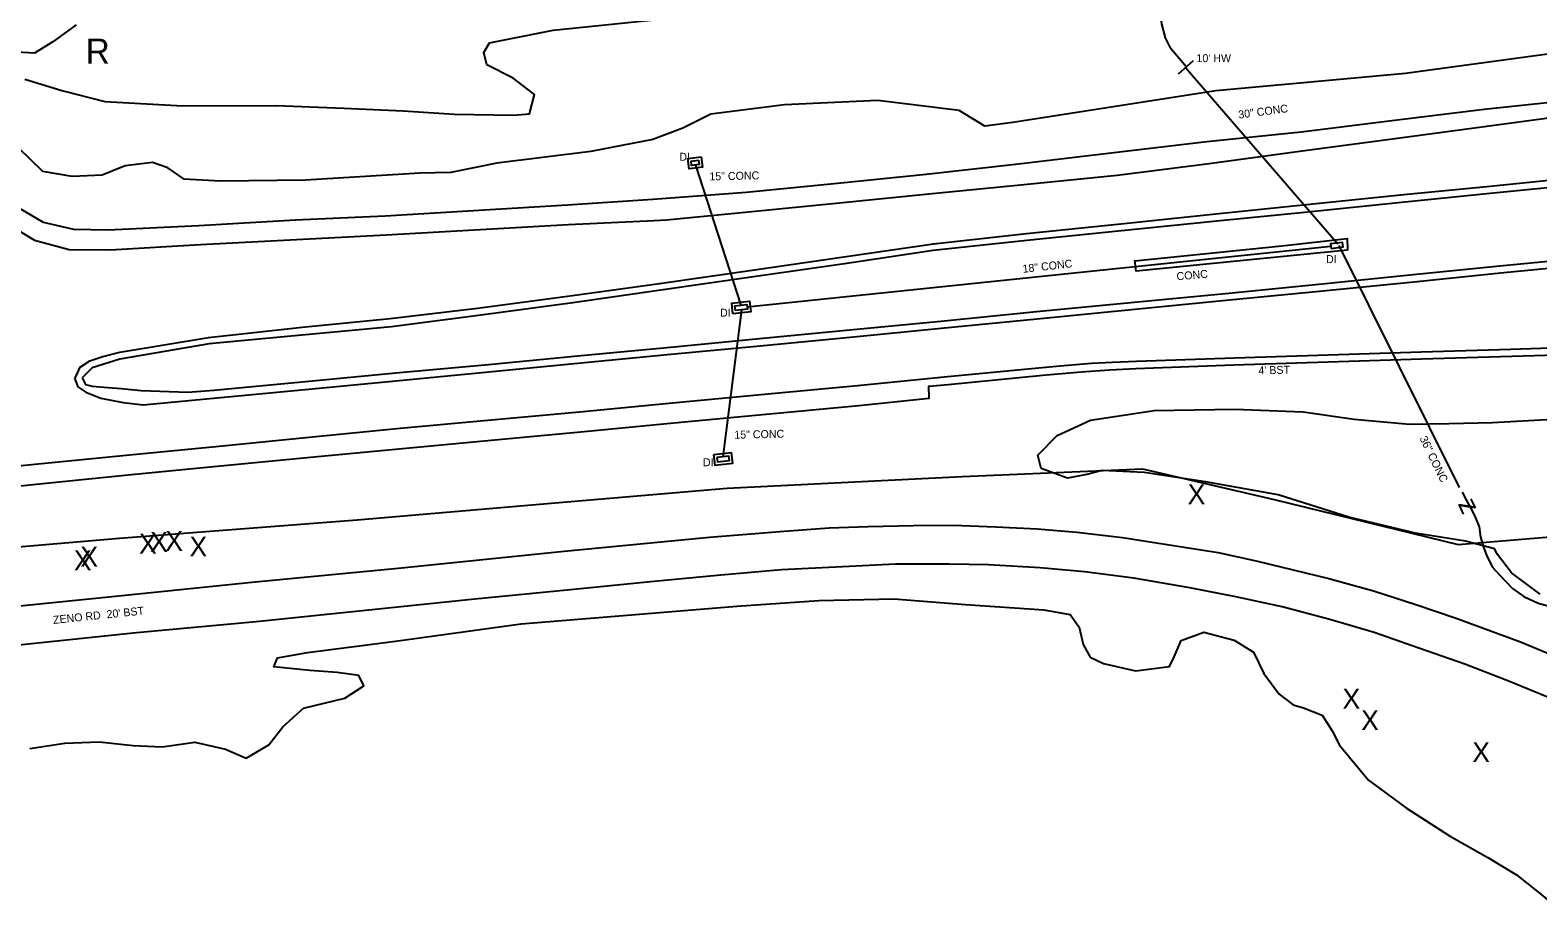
# Model space of a CAD drawing. Extents: x 2030130 to 2036320, y 723205 to 762423.
# Drawn here: x 2035001 to 2035759, y 726845 to 727287 of the extents above; entities that cross this region are included whole.
import ezdxf

# ---------------------------------------------------------------- set-up
doc = ezdxf.new("R2010")
doc.units = 0
for name, color, linetype in [('Draft_Station Labels Major', 7, 'Continuous'), ('Draft_Station Tics Major', 7, 'Continuous'), ('Draft_Station Tics Minor', 7, 'Continuous'), ('Exist Terrain Model Ground Surface', 7, 'Continuous'), ('Old_Level_23', 7, 'Continuous'), ('Old_Level_26', 7, 'Continuous'), ('Prop Alignment Horizontal', 7, 'Continuous'), ('Prop Horizontal Alignment Ramp', 7, 'Continuous')]:
    doc.layers.add(name, color=color, linetype=linetype)

msp = doc.modelspace()

# ---------------------------------------------------------------- linework, layer by layer
at = {"layer": 'Draft_Station Labels Major'}
for points in [[(2034995.67, 727197.76), (2035007.95, 727190.6), (2035023.23, 727187.12), (2035040.54, 727186.77), (2035086.21, 727188.91), (2035134.73, 727191.73), (2035179.77, 727193.68), (2035224.16, 727196.39), (2035271.27, 727199.24), (2035314.12, 727202.1), (2035361.03, 727205.55), (2035406.96, 727210.09), (2035451.37, 727214.71), (2035497.79, 727219.82), (2035545.59, 727225.46), (2035592.34, 727230.99), (2035639.71, 727235.89), (2035686.58, 727241.72), (2035731.7, 727247.24), (2035777.53, 727252.23)], [(2034987.95, 727191.14), (2035003.56, 727181.45), (2035021.04, 727176.81), (2035041.57, 727176.7), (2035086.95, 727179.28), (2035135.13, 727181.86), (2035180.16, 727184.26), (2035224.63, 727186.74), (2035271.82, 727189.31), (2035314.77, 727191.4), (2035320.99, 727191.67), (2035362.13, 727195.75), (2035407.9, 727200.25), (2035452.82, 727204.72), (2035498.77, 727209.24), (2035547.35, 727214.24), (2035593.63, 727219.94), (2035640.31, 727226.31), (2035688.19, 727232.77), (2035733, 727238.8), (2035777.64, 727244.71)], [(2035023.82, 727111.95), (2035026.5, 727117.79), (2035031.4, 727121.01), (2035037.9, 727123.09), (2035046.5, 727125.3), (2035091, 727132.65), (2035137.96, 727137.91), (2035182.15, 727142.13), (2035226.08, 727147.42), (2035273.83, 727153.8), (2035317.56, 727159.8), (2035364.11, 727166.47), (2035411.17, 727173.29), (2035455.14, 727179.73), (2035501.75, 727184.87), (2035549.16, 727189.76), (2035596.84, 727194.69), (2035642.48, 727199.49), (2035691.26, 727204.45), (2035734.59, 727208.7), (2035782.17, 727213.41)], [(2035782.01, 727209.72), (2035734.61, 727205), (2035691.81, 727200.57), (2035643.12, 727195.66), (2035597.36, 727191.03), (2035549.5, 727186.19), (2035501.94, 727181.35), (2035455, 727176.3), (2035411.56, 727169.82), (2035364.62, 727163.13), (2035318.19, 727156.47), (2035274.04, 727150.05), (2035226.67, 727143.76), (2035182.88, 727137.95), (2035137.89, 727133.79), (2035091.4, 727129.43), (2035046.51, 727121.81), (2035032.52, 727117.35), (2035027.61, 727112.33)], [(2035027.61, 727112.33), (2035029.24, 727109.03), (2035032.51, 727108.18), (2035038.43, 727107.77), (2035047.08, 727107.02), (2035057.18, 727106.07), (2035080.54, 727105.13), (2035093.62, 727106.19), (2035139.79, 727110.55), (2035185.09, 727114.88), (2035231.65, 727119.04), (2035278.17, 727123.64), (2035323.02, 727127.87), (2035367.66, 727132.16), (2035414.75, 727136.6), (2035458.8, 727140.86), (2035506.9, 727145.71), (2035554.25, 727150.24), (2035603.45, 727154.94), (2035650.24, 727159.62), (2035696.03, 727164.21), (2035741.21, 727168.77), (2035786.41, 727173.12)], [(2035023.82, 727111.95), (2035025.39, 727107.83), (2035029.35, 727105.26), (2035036.9, 727102.26), (2035048.18, 727099.99), (2035058.18, 727098.79), (2035093.58, 727102.23), (2035139.53, 727106.62), (2035185, 727110.89), (2035231.85, 727115.39), (2035278.09, 727119.87), (2035323.23, 727124.21), (2035367.97, 727128.51), (2035414.99, 727133.03), (2035459.02, 727137.29), (2035507.2, 727142.06), (2035554.49, 727146.63), (2035603.74, 727151.53), (2035650.62, 727156.11), (2035696.41, 727160.59), (2035741.57, 727165.24), (2035786.6, 727169.71)], [(2034960.25, 727064.7), (2035005.43, 727069.15), (2035051.36, 727073.76), (2035096.33, 727078.17), (2035141.5, 727082.54), (2035187.29, 727087.06), (2035233.15, 727091.27), (2035279.08, 727095.56), (2035324, 727099.79), (2035370.27, 727104.21), (2035416.85, 727108.6), (2035462.11, 727113.1), (2035509.67, 727117.57), (2035520.57, 727118.57), (2035534.52, 727119.69), (2035544.99, 727120.25), (2035557.08, 727120.75), (2035606.35, 727122.42), (2035653.26, 727123.93), (2035699.99, 727125.39), (2035745.08, 727126.81), (2035790.2, 727128.27)], [(2034961.1, 727054.42), (2035006.09, 727059.13), (2035052.31, 727063.9), (2035097.05, 727068.15), (2035142.24, 727072.54), (2035188.35, 727076.86), (2035234.75, 727081.2), (2035279.66, 727085.39), (2035324.74, 727089.82), (2035371.11, 727094.1), (2035417.66, 727098.44), (2035452.86, 727102.11), (2035452.82, 727108.22), (2035462.52, 727108.98), (2035510.06, 727113.76), (2035529.18, 727115.44), (2035543.51, 727116.48), (2035556.77, 727117.16), (2035605.94, 727118.88), (2035653.34, 727120.46), (2035700.25, 727121.9), (2035745.52, 727123.36), (2035790.68, 727124.55)], [(2034964.59, 726994.74), (2035044.23, 727002.78), (2035112.72, 727009.77), (2035186.17, 727016.86), (2035269.65, 727025.31), (2035342.58, 727032.46), (2035377.97, 727035.21), (2035402.75, 727037.03), (2035422.25, 727037.7), (2035445.03, 727038.2), (2035464.97, 727038.41), (2035486.44, 727037.59), (2035507.23, 727036.63), (2035527.03, 727034.85), (2035550.06, 727032.25), (2035572.43, 727028.74), (2035598.13, 727024.62), (2035617.8, 727020.33), (2035653.62, 727011.71), (2035676.02, 727005.4), (2035697.39, 726998.64), (2035717.56, 726991.74), (2035749.83, 726979.87), (2035770.85, 726971.22)], [(2035766.73, 726950.75), (2035743.56, 726960.22), (2035721.92, 726968.67), (2035698.93, 726976.69), (2035676.48, 726984.47), (2035654.17, 726991.11), (2035630.24, 726997.36), (2035606.99, 727002.36), (2035583.85, 727006.92), (2035555.63, 727011.76), (2035530.99, 727014.99), (2035508.73, 727017.04), (2035482.78, 727018.52), (2035463.09, 727018.85), (2035436.05, 727018.79), (2035409.42, 727017.5), (2035378.8, 727015.92), (2035348.37, 727013.33), (2035313, 727009.95), (2035274.5, 727006.07), (2035223, 727001.03), (2035176.37, 726996.33), (2035114.89, 726989.95), (2035054.86, 726984.31), (2034992.56, 726977.82)]]:
    msp.add_lwpolyline(points, dxfattribs=at)
at = {"layer": 'Draft_Station Tics Major'}
for points in [[(2034998.7, 727262.4), (2035017.39, 727256.65), (2035038.86, 727251.12), (2035078.17, 727248.92), (2035125.22, 727249.2), (2035159, 727247.85), (2035188.84, 727246.41), (2035214.36, 727244.82), (2035244.09, 727244.25), (2035252.17, 727244.99), (2035254.69, 727254.61), (2035243.92, 727262.86), (2035230.85, 727269.48), (2035229.33, 727275.68), (2035232.18, 727280.56), (2035264.12, 727286.9), (2035324.53, 727293.15)], [(2035024.58, 727289.56), (2035012.73, 727281.15), (2035003.67, 727275.38), (2034988.97, 727276.19)], [(2035769.64, 727275.69), (2035692.2, 727265.24), (2035596.89, 727256.49), (2035494.99, 727240.56), (2035480.86, 727238.7), (2035468.03, 727246.57), (2035427.22, 727251.65), (2035380.35, 727249.47), (2035343.29, 727244.74), (2035329.16, 727237.71), (2035314.15, 727232.11), (2035282.93, 727226.11), (2035235.82, 727220.15), (2035212.72, 727215.53), (2035197.14, 727215.09), (2035139.77, 727211.62), (2035097.03, 727211.17), (2035078.78, 727212.19), (2035070.57, 727217.81), (2035062.85, 727220.44), (2035049.13, 727218.89), (2035037.6, 727214.09), (2035022.49, 727213.45), (2035007.82, 727216.05), (2034995.89, 727227.54)], [(2035759.72, 727003.84), (2035745.4, 727014.46), (2035738.28, 727023.66), (2035736.77, 727026.6), (2035722.34, 727030.38), (2035697.21, 727034.45), (2035663.76, 727042.47), (2035628.2, 727053.61), (2035591.74, 727060.18), (2035560.98, 727064.95), (2035539.82, 727065.87), (2035532.16, 727063.85), (2035522.48, 727062.09), (2035509.21, 727066.84), (2035507.42, 727073.57), (2035517.19, 727083.38), (2035533.97, 727091.18), (2035565.92, 727095.93), (2035606.46, 727096.75), (2035640.77, 727095.28), (2035666.42, 727091.59), (2035694.2, 727089.2), (2035714.14, 727089.41), (2035735.9, 727089.91), (2035769.03, 727091.8)], [(2035001.3, 726926.37), (2035018.77, 726929.02), (2035036.11, 726929.62), (2035053.12, 726927.75), (2035067.67, 726927.17), (2035084.1, 726929.5), (2035099.59, 726925.92), (2035109.84, 726921.43), (2035121.21, 726928.06), (2035128.27, 726937.09), (2035138.78, 726946.54), (2035159.54, 726951.57), (2035169.05, 726957.71), (2035166.51, 726962.89), (2035155.53, 726964.48), (2035141.95, 726965.49), (2035123.87, 726967.23), (2035125.68, 726971.73), (2035140.66, 726974.45), (2035184.86, 726980.19), (2035248.03, 726988.89), (2035307.4, 726993.75), (2035356.29, 726997.7), (2035397.46, 727000.64), (2035435.19, 727001.44), (2035471.14, 726998.57), (2035510.44, 726995.86), (2035523.74, 726993.54), (2035528.22, 726987.2), (2035530.31, 726978.46), (2035533.7, 726972.11), (2035540.53, 726968.99), (2035556.54, 726965.34), (2035573.7, 726967.45), (2035575.97, 726972.38), (2035579.42, 726980.59), (2035590.85, 726984.67), (2035606.14, 726980.67), (2035615.8, 726974.71), (2035621.07, 726964), (2035628.66, 726953.64), (2035635.7, 726948.25), (2035640.99, 726946.73), (2035650.25, 726942.96), (2035655.28, 726935.22), (2035659.04, 726927.96), (2035673.64, 726910.36), (2035692.64, 726896.36), (2035714.19, 726882.41), (2035733.52, 726871.51), (2035747.91, 726862.88), (2035758.44, 726854.54), (2035770.41, 726844.78)]]:
    msp.add_lwpolyline(points, dxfattribs=at)
at = {"layer": 'Draft_Station Tics Minor'}
for p, q in [((2035578.2, 727264.97), (2035585.63, 727271.66)), ((2035335.51, 727219.23), (2035358.41, 727148.87)), ((2035361.54, 727148), (2035654.67, 727178.53)), ((2035358.66, 727146.51), (2035349.35, 727072.71))]:
    msp.add_line(p, q, dxfattribs=at)
for points in [[(2035581.89, 727268.12), (2035658.24, 727179.69)], [(2035658.63, 727178.91), (2035719.09, 727057.27)]]:
    msp.add_lwpolyline(points, dxfattribs=at)
for points in [[(2035337.11, 727221.68), (2035337.4, 727219.48), (2035333.62, 727218.98), (2035333.33, 727221.18)], [(2035663.1, 727176.42), (2035556.83, 727165.95), (2035556.19, 727171.16), (2035630.09, 727178.75), (2035662.88, 727182.39)], [(2035654.8, 727177.39), (2035660.85, 727178.1), (2035660.59, 727180.38), (2035654.54, 727179.66)], [(2035355.65, 727146.2), (2035355.4, 727148.55), (2035361.42, 727149.18), (2035361.67, 727146.83)], [(2035346.34, 727072.37), (2035346.58, 727070.21), (2035352.61, 727070.88), (2035352.37, 727073.05)]]:
    msp.add_lwpolyline(points, close=True, dxfattribs=at)
at = {"layer": 'Exist Terrain Model Ground Surface'}
for points in [[(2035338.4, 727223.36), (2035339.09, 727218.19), (2035332.33, 727217.3), (2035331.65, 727222.47)], [(2035354.31, 727144.55), (2035353.76, 727149.89), (2035362.76, 727150.83), (2035363.31, 727145.49)], [(2035344.68, 727073.7), (2035345.25, 727068.55), (2035354.27, 727069.56), (2035353.69, 727074.71)]]:
    msp.add_lwpolyline(points, close=True, dxfattribs=at)
msp.add_lwpolyline([(2034965.98, 727025.07), (2035046.29, 727031.85), (2035165.59, 727041.12), (2035265.08, 727049.68), (2035351.44, 727057.07), (2035469.57, 727062.82), (2035560.06, 727066.76), (2035626.11, 727051.39), (2035718.65, 727028.67), (2035867.23, 727041.07)], dxfattribs=at)
at = {"layer": 'Prop Alignment Horizontal'}
for points in [[(2035525.93, 727354.86), (2035529.54, 727349.67), (2035532.33, 727346.97), (2035535.98, 727344.7), (2035540.31, 727342.64), (2035546.93, 727339.88), (2035552.05, 727337.21), (2035554.64, 727335.13), (2035558.45, 727332.1), (2035560.7, 727329.01), (2035563.06, 727324.57), (2035563.2, 727319.73), (2035564.07, 727312.13), (2035566.18, 727305.97), (2035568.36, 727297.75), (2035569.68, 727290.14), (2035571.5, 727283.18), (2035573.83, 727278.48), (2035582.11, 727268.58)], [(2035720.67, 727054.95), (2035722.71, 727050.84), (2035725.6, 727045.56), (2035727.37, 727042.12), (2035729.21, 727037.54), (2035729.85, 727032.37), (2035731.29, 727027.42), (2035732.92, 727022.94), (2035735.91, 727017.41), (2035739.18, 727013.71), (2035745.88, 727006.66), (2035751.51, 727002.54), (2035758.75, 726999.33), (2035768.65, 726996.5), (2035785.26, 726992.14), (2035827.88, 726980.51), (2035848.11, 726973.83), (2035861.42, 726970.85), (2035867.87, 726968.37), (2035873.96, 726965.27)]]:
    msp.add_lwpolyline(points, dxfattribs=at)

# ---------------------------------------------------------------- texts
at = {"layer": 'Draft_Station Tics Major'}
for p in [(2035582.72, 727048.95), (2035061.67, 727025.01), (2035069.27, 727025.5), (2035026.6, 727017.59), (2035056.11, 727024.08), (2035081.41, 727022.71), (2035023.39, 727015.73), (2035660.5, 726946.28), (2035669.86, 726935.5), (2035725.67, 726919.44)]:
    msp.add_text('X', height=10, dxfattribs=at).set_placement(p)
at = {"layer": 'Old_Level_23'}
for s, rotation, p in [("4' BST", 1.31749, (2035618.33, 727114.13)), ("ZENO RD  20' BST", 5.96367, (2035013.12, 726988.82))]:
    msp.add_text(s, height=4, rotation=rotation, dxfattribs=at).set_placement(p)
at = {"layer": 'Old_Level_26'}
for s, rotation, p in [("10' HW", 0.00002, (2035587.17, 727270.91)), ('30" CONC', 7.51136, (2035608.46, 727242.53)), ('15" CONC', 1.28191, (2035342.56, 727211.51)), ('18" CONC', 6.46381, (2035500.08, 727165.1)), ('CONC', 4.99977, (2035577.35, 727161.32)), ('15" CONC', 1.28191, (2035355.08, 727081.8)), ('36" CONC', 295.9312, (2035699.1, 727082.02))]:
    msp.add_text(s, height=4, rotation=rotation, dxfattribs=at).set_placement(p)
for p in [(2035327.45, 727221.39), (2035652.23, 727170.02), (2035347.88, 727143.1), (2035339.3, 727068)]:
    msp.add_text('DI', height=4, dxfattribs=at).set_placement(p)
at = {"layer": 'Prop Alignment Horizontal'}
msp.add_text('z', height=10, rotation=295.88553, dxfattribs=at).set_placement((2035718.22, 727049.15))
at = {"layer": 'Prop Horizontal Alignment Ramp'}
msp.add_text('R', height=12.5, dxfattribs=at).set_placement((2035029.33, 727270.22))

doc.saveas('drawing.dxf')
